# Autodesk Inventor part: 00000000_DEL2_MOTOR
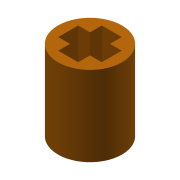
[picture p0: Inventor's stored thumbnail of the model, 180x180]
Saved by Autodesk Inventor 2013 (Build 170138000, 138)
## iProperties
Created: 2013-03
Part Number: 00000000_DEL2_MOTOR
Material: Generic
Document SubType Name: Modeling
Designer: perblt
Density: 1 g/cm^3
Translation Standard: STEP AP203
FileName: 00000000_DEL2_MOTOR
PreProcessor: PRO/ENGINEER BY PARAMETRIC TECHNOLOGY CORPORATION, 2010370
PostProcessor: Build: 138, Release: 2013 RTM - Date: Thu 03/01/2012
Sent Units: millimeter
Uncertainty: 0.001208204538419
Author: perblt
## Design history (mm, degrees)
node "00000000_DEL2_MOTOR1"
sketch "Sketch1"
  geometry: L1 (-1.449, 1.449)-(-1.449, 1.913) reference; L2 (1.449, 1.913)-(1.449, 1.449) reference; L3 (1.449, 1.449)-(1.913, 1.449) reference; L4 (1.913, -1.449)-(1.449, -1.449) reference; L5 (1.449, -1.449)-(1.449, -1.913) reference; L6 (-1.449, -1.913)-(-1.449, -1.449) reference; L7 (-1.449, -1.449)-(-1.913, -1.449) reference; L8 (-1.913, 1.449)-(-1.449, 1.449) reference; L9 (1, -2.182)-(-1, -2.182); L10 (-1, 2.182)-(1, 2.182); L11 (1, -2.182)-(-1, 2.182); L12 (-1, -2.182)-(1, 2.182); L13 (-2.182, -1)-(-2.182, 1); L14 (2.182, 1)-(2.182, -1); L15 (2.182, -1)-(-2.182, 1); L16 (-2.182, -1)-(2.182, 1); L17 (-1, -2.182)-(-1, -1); L18 (-1, 1)-(-1, 2.182); L19 (2.182, -1)-(1, -1); L20 (-1, -1)-(-2.182, -1); L21 (1, 2.182)-(1, 1); L22 (1, -1)-(1, -2.182); L23 (-2.182, 1)-(-1, 1); L24 (1, 1)-(2.182, 1); C1 r 2.769 at (0, 0); A1 r 2.4 centre (0, 0) between (1.449, 1.913) and (-1.449, 1.913) reference; A2 r 2.4 centre (0, 0) between (1.913, -1.449) and (1.913, 1.449) reference; A3 r 2.4 centre (0, 0) between (-1.449, -1.913) and (1.449, -1.913) reference; A4 r 2.4 centre (0, 0) between (-1.913, 1.449) and (-1.913, -1.449) reference
  constraints: 38 end point, 10 parallel, 4 perpendicular, 3 horizontal, 2 point on circle, 1 centre point, 1 coincident
extrude "Extrusion1" join sketch "Sketch1" distance "d3" = 8; taper "d4" = 0 deg
node "00000000_DEL2_MOTOR"
node "Base1"
other parameters: "d0" = 4.8
